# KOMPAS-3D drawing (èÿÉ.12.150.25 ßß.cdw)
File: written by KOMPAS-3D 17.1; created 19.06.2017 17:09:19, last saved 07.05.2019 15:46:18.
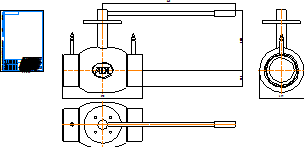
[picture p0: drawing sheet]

Sheet 1: A4, portrait

Title block, sheet 1: name: КШР.12.150.25 сс; material: Внимание! Данный продукт является объектом авторского права ООО «Торговый Дом АДЛ». / Запрещается изменение, копирование, распространение / (в том числе путем копирования на другие сайты и ресурсы в Интернете) / или любое иное использование информации и объектов без предварительного / согласия правообладателя (ООО «Торговый Дом АДЛ»).; scale: 1:1; sheets: 1; organisation: ООО "Торговый дом АДЛ"; sheet format: A4; stored path: C:\Users\tra\Desktop\2д чертежи\Шаровые краны БИВАЛ\КШР_Бивал_серия_12\KOMPAS 2D\КШР.12.150.25 сс.cdw

Views: Спереди 1, Проекционный вид 2, Проекционный вид 3
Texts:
  Klimkovich
  ADL
Dimensions and other numbers on the sheet: 390; 645; 291,6; 79,5; 219; 1:1; 1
